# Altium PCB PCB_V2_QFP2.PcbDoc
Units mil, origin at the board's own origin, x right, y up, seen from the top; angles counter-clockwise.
Board outline 5390 x 3140 mil, 2 copper layers (Top Layer, Bottom Layer); 72 components, 66 nets, 285 pads, 52 vias.
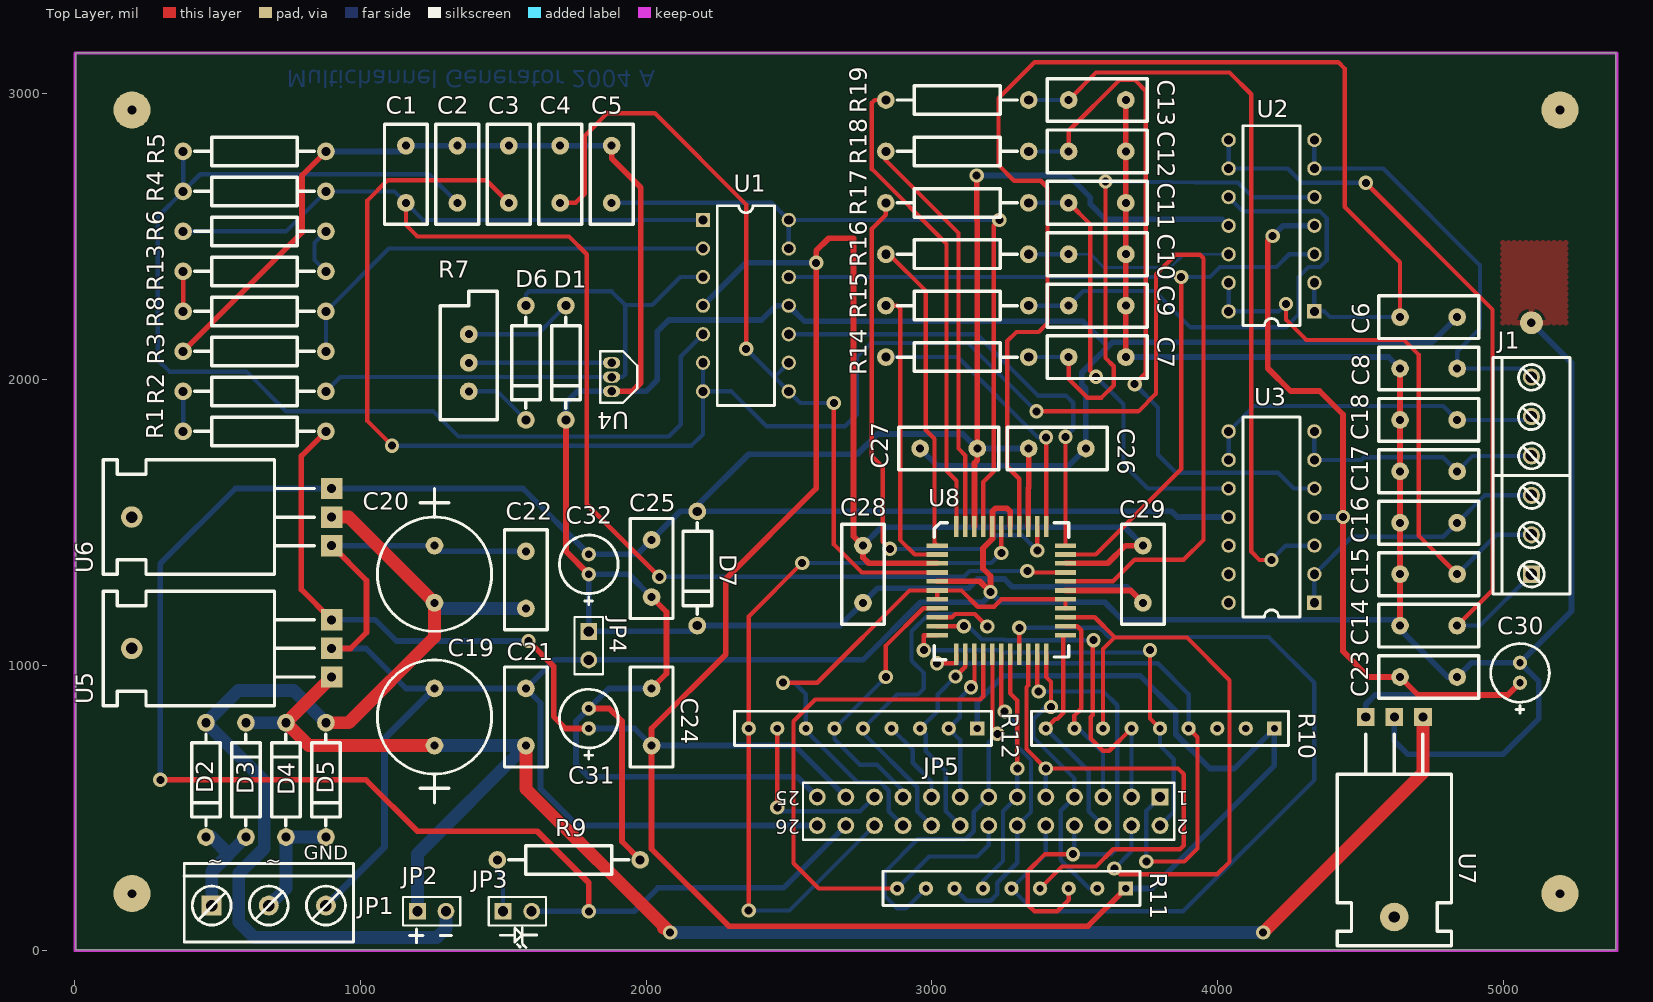
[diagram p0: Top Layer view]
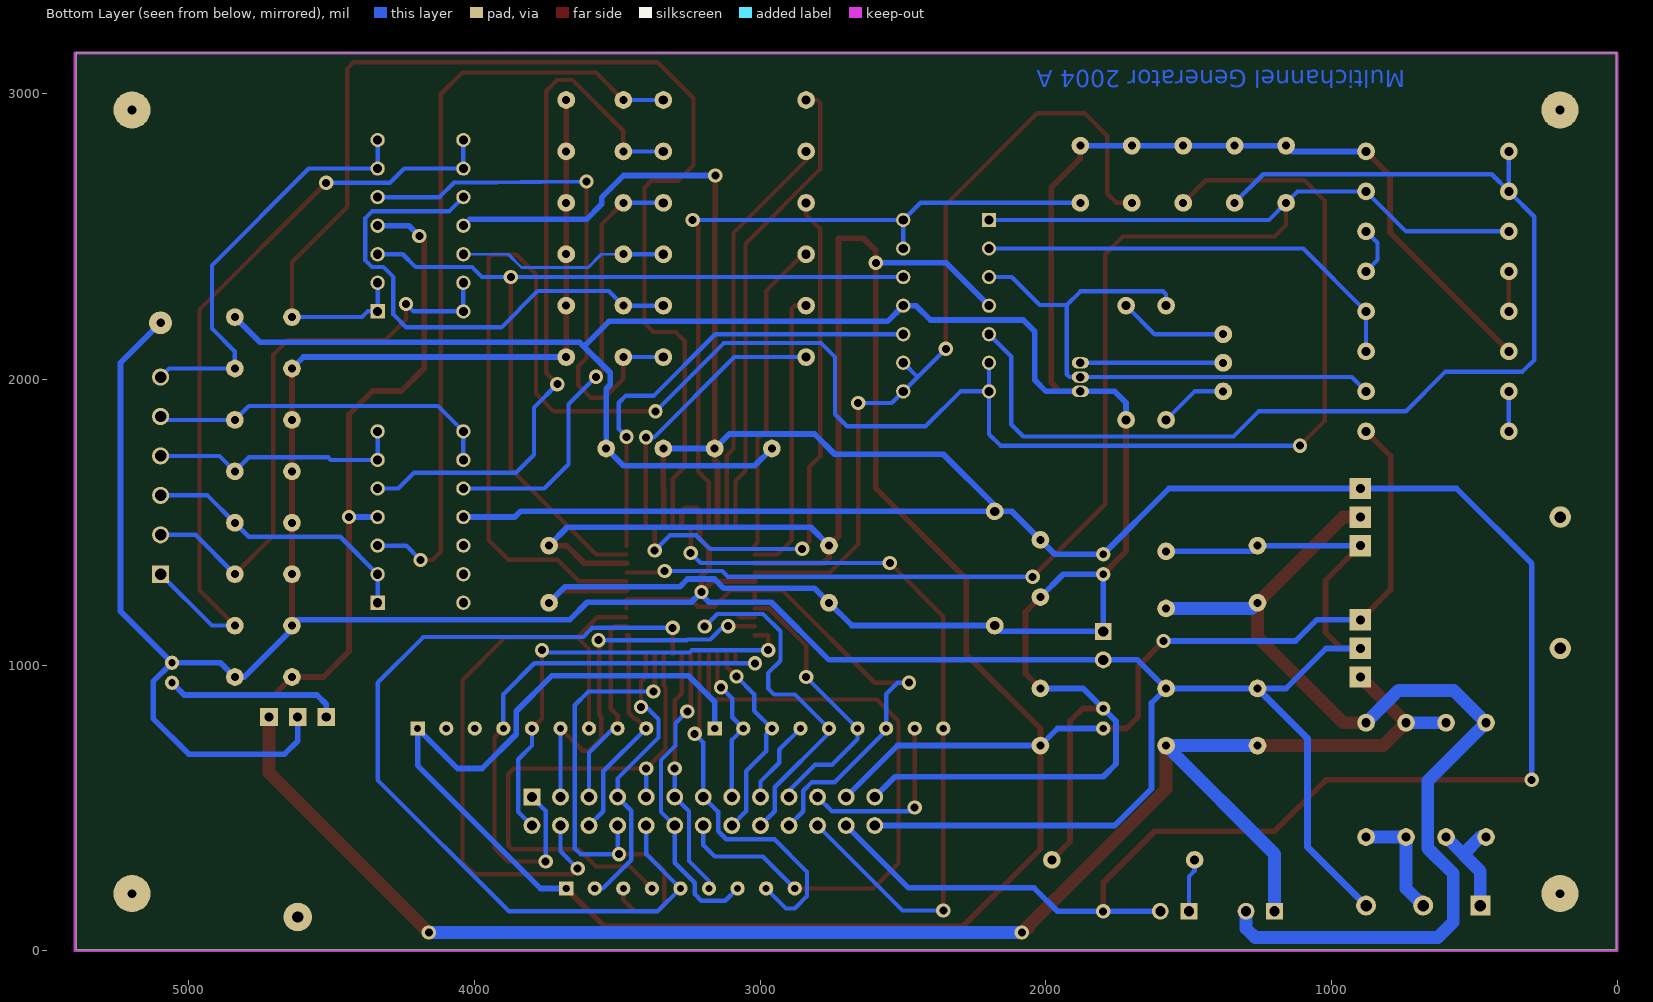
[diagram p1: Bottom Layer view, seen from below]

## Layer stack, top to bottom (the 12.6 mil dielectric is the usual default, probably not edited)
Top Layer: signal copper 1.4
Dielectric: dielectric 12.6, FR-4, Dk 4.8
Bottom Layer: signal copper 1.4

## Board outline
4,3 5394,3 5394,3143 4,3143

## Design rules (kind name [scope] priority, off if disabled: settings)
Clearance [All] p1: gap=10
ComponentClearance [All] p1: gap=10 collisioncheckmode=0
FanoutControl Fanout_SIP [IsSIP] p1: bgadir=In bgaviamode=Closest fanoutstyle=UnderPads fanoutdirection=OutOnly viagrid=1
FanoutControl Fanout_DIP [IsDIP] p2: bgadir=In bgaviamode=Closest fanoutstyle=UnderPads fanoutdirection=OutOnly viagrid=1 // Bez komentarza
FanoutControl Fanout_LCC [IsLCC] p3: bgadir=In bgaviamode=Closest fanoutstyle=Auto fanoutdirection=OutOnly viagrid=1 // Fanout_LCC (Default Rule)
FanoutControl Fanout_BGA [IsBGA] p4: bgadir=Out bgaviamode=Centered fanoutstyle=Auto fanoutdirection=Alternating viagrid=1 // Fanout_BGA (Default Rule)
FanoutControl Fanout_SOIC [IsSOIC] p5: bgadir=Out bgaviamode=Closest fanoutstyle=Auto fanoutdirection=Alternating viagrid=1 // Fanout_SOIC (Default Rule)
FanoutControl Fanout_Default [All] p6: bgadir=Out bgaviamode=Centered fanoutstyle=Auto fanoutdirection=None viagrid=1 // Fanout_Default (Default Rule)
PolygonConnect [All] p1: connectstyle=Relief reliefconductorwidth=10 reliefentries=4 polygonreliefangle="90 Angle"
RoutingLayers [All] p1: top layer=Vertical bottom layer=Horizontal
RoutingVias [All] p1: holewidth=28 width=50 viastyle="Through Hole" minholewidth=28 minwidth=50 maxholewidth=28 maxwidth=50
SolderMaskExpansion [All] p1: expansion=4
TestPointUsage [All] p1: valid=0 allowmultiple=FALSE
Testpoint [All] p1: side=15 testpointundercomponent=TRUE minsize=40 maxsize=100 preferedsize=60 minholesize=0 maxholesize=40 preferedholesize=32 testpointgrid=1 style=1023 order=1234567890
Width 20mil [InNet('VDD') + InNet('VSS') + InNet('AGND') + InNet('GND')+ InNet('+9V')] p1: maxlimit=30 minlimit=10 preferedwidth=10 toplayer_minwidth=15 toplayer_prefwidth=20 bottomlayer_minwidth=15 bottomlayer_prefwidth=20 minimp=50.000000 maximp=50.000000 favimp=50.000000
Width 45mil [InNet('POWER+') + InNet('POWER-') + InNet('POWERA') + InNet('POWERB') + InNet('POWERC') + InNet('POWERD')+ InNet('Net_LM7805')+ InNet('Net_LM7905')] p2: maxlimit=50 minlimit=10 preferedwidth=10 toplayer_minwidth=40 toplayer_prefwidth=45 bottomlayer_minwidth=40 bottomlayer_prefwidth=45 minimp=50.000000 maximp=50.000000 favimp=50.000000
Width 15mil [All] p3: maxlimit=20 minlimit=10 preferedwidth=10 toplayer_prefwidth=15 bottomlayer_prefwidth=15 minimp=50.000000 maximp=50.000000 favimp=50.000000
11 further rules are at their usual default settings.

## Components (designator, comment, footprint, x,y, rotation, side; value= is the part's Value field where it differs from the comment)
C1 "10nF" RAD0.2 1159,2618 r90 top
C2 "10nF" RAD0.2 1339,2618 r90 top
C3 "10nF" RAD0.2 1519,2618 r90 top
C4 "10nF" RAD0.2 1699,2618 r90 top
C5 "10nF" RAD0.2 1879,2618 r90 top
C6 "10nF" RAD0.2 4639,2218 r0 top
C7 "100pF" RAD0.2 3479,2078 r0 top
C8 "100pF" RAD0.2 4839,2038 r180 top
C9 "100pF" RAD0.2 3479,2258 r0 top
C10 "100pF" RAD0.2 3479,2438 r0 top
C11 "100pF" RAD0.2 3479,2618 r0 top
C12 "100pF" RAD0.2 3479,2798 r0 top
C13 "100pF" RAD0.2 3479,2978 r0 top
C14 "100pF" RAD0.2 4839,1138 r180 top
C15 "100pF" RAD0.2 4839,1318 r180 top
C16 "100pF" RAD0.2 4839,1498 r180 top
C17 "100pF" RAD0.2 4839,1678 r180 top
C18 "100pF" RAD0.2 4839,1858 r180 top
C19 "220uF" RB.2/.4 1259,718 r270 top
C20 "220uF" RB.2/.4 1259,1418 r90 top
C21 "100nF" RAD0.2 1579,918 r270 top
C22 "100nF" RAD0.2 1579,1198 r90 top
C23 "100nF" RAD0.2 4839,958 r180 top
C24 "100nF" RAD0.2 2019,918 r270 top (schematic designator C23)
C25 "100nF" RAD0.2 2019,1438 r270 top (schematic designator C24)
C26 "100nF" RAD0.2 3339,1758 r0 top (schematic designator C25)
C27 "100nF" RAD0.2 3159,1758 r180 top (schematic designator C26)
C28 "100nF" RAD0.2 2759,1418 r270 top (schematic designator C27)
C29 "100nF" RAD0.2 3739,1418 r270 top (schematic designator C28)
C30 "10uF" RB.07/.2 5059,938 r90 top
C31 "10uF" RB.07/.2 1799,778 r90 top (schematic designator C29)
C32 "10uF" RB.07/.2 1799,1318 r90 top (schematic designator C30)
D1 "1N4148" DIODE0.4 1719,2258 r270 top
D2 "1N4001" DIODE0.4 459,798 r270 top
D3 "1N4001" DIODE0.4 599,398 r90 top
D4 "1N4001" DIODE0.4 739,398 r90 top
D5 "1N4001" DIODE0.4 879,798 r270 top
D6 "1N4181" DIODE0.4 1579,2258 r270 top
D7 "Schottky" Diode0.4 2179,1538 r270 top
J1 "Term6" TERM6-0.14 5099,1318 r90 top
JP1 "Header 3X1" TERM3-0.2 479,158 r0 top
JP2 "Header 2X1" HDR1X2 1199,138 r0 top
JP3 "Header 2X1" HDR1X2 1499,138 r0 top
JP4 "Header 2X1" HDR1X2 1799,1118 r270 top
JP5 "Header 13X2" HDR2X13 3799,538 r180 top
R1 "100" AXIAL0.5 379,1818 r0 top
R2 "2.4k" AXIAL0.5 879,1958 r180 top
R3 "10k" AXIAL0.5 879,2098 r180 top
R4 "10k" AXIAL0.5 379,2658 r0 top
R5 "10k" AXIAL0.5 879,2798 r180 top
R6 "15k" AXIAL0.5 379,2518 r0 top
R7 "10k" VR5 1379,1958 r90 top
R8 "330" AXIAL0.5 879,2238 r180 top
R9 "330" AXIAL0.5 1979,318 r180 top
R10 "RPACK8" RPACK8 4199,778 r270 top
R11 "RPACK8" RPACK8 3679,218 r270 top
R12 "RPACK8" RPACK8 3159,778 r270 top
R13 "1k2" AXIAL0.5 379,2378 r0 top
R14 "750" AXIAL0.5 2839,2078 r0 top
R15 "750" AXIAL0.5 3339,2258 r180 top
R16 "750" AXIAL0.5 3339,2438 r180 top
R17 "750" AXIAL0.5 3339,2618 r180 top
R18 "750" AXIAL0.5 3339,2798 r180 top
R19 "750" AXIAL0.5 3339,2978 r180 top
U1 "TL084" DIP14 2199,2558 r0 top locked
U2 "LM324" DIP14 4339,2238 r180 top
U3 "LM324" DIP14 4339,1218 r180 top
U4 "LM336Z2.5(3)" TO-92B 1879,1958 r90 top
U5 "LM7805CT" TO-220#1 899,958 r90 top
U6 "LM7905CT" TO-220#1 899,1418 r90 top
U7 "LM7809C" TO-220#2 4719,818 r180 top
U8 "MAX547-QFP44" QFP44-2 3019,1418 r0 top (schematic designator U7)

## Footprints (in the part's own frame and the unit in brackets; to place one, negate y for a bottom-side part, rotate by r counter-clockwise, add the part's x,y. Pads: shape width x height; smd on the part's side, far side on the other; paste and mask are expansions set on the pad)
AXIAL0.5 [mil]
  round 62 hole 32: 1(0,0) 2(500,0)
  silkscreen extent 40,-50 460,50
DIODE0.4 [mil]
  round 62 hole 32: 1(0,0) 2(400,0)
  silkscreen extent 40,-50 360,50
Diode0.4 [mil]
  round 62 hole 32: 1(0,0) 2(400,0)
  silkscreen extent 40,-50 360,50
DIP14 [mil]
  rect 50x50 hole 32: 1(0,0)
  round 50 hole 32: 2(0,-100) 3(0,-200) 4(0,-300) 5(0,-400) 6(0,-500) 7(0,-600) 8(300,-600) 9(300,-500) 10(300,-400) 11(300,-300) 12(300,-200) 13(300,-100) 14(300,0)
  silkscreen extent 50,-650 250,50
HDR1X2 [mm]
  rect 1.5x1.5 hole 0.9: 1(0,0)
  round 1.5 hole 0.9: 2(2.54,0)
  silkscreen extent -1.27,-1.27 3.81,1.27
HDR2X13 [mm]
  rect 1.5x1.5 hole 0.9: 1(0,0)
  round 1.5 hole 0.9: 2(0,2.54) 3(2.54,0) 4(2.54,2.54) 5(5.08,0) 6(5.08,2.54) 7(7.62,0) 8(7.62,2.54) 9(10.16,0) 10(10.16,2.54) 11(12.7,0) 12(12.7,2.54) 13(15.24,0) 14(15.24,2.54) 15(17.78,0) 16(17.78,2.54) 17(20.32,0) 18(20.32,2.54) 19(22.86,0) 20(22.86,2.54) 21(25.4,0) 22(25.4,2.54) 23(27.94,0) 24(27.94,2.54) 25(30.48,0) 26(30.48,2.54)
  silkscreen extent -1.27,-1.27 31.75,3.81
QFP44-2 [mil]
  rect 75x16 smd: 1(0,0) 2(0,-31) 3(0,-62) 4(0,-94) 5(0,-125) 6(0,-157) 7(0,-188) 8(0,-219) 9(0,-251) 10(0,-282) 11(0,-314) 23(449,-314) 24(449,-282) 25(449,-251) 26(449,-219) 27(449,-188) 28(449,-157) 29(449,-125) 30(449,-94) 31(449,-62) 32(449,-31) 33(449,0)
  rect 16x75 smd: 12(67,-381) 13(98,-381) 14(130,-381) 15(161,-381) 16(193,-381) 17(224,-381) 18(255,-381) 19(287,-381) 20(318,-381) 21(350,-381) 22(381,-381) 34(381,67) 35(350,67) 36(318,67) 37(287,67) 38(255,67) 39(224,67) 40(193,67) 41(161,67) 42(130,67) 43(98,67) 44(67,67)
  silkscreen extent -10,-400 460,80
RAD0.2 [mil]
  round 62 hole 28: 1(0,0) 2(200,0)
  silkscreen extent -75,-75 275,75
RB.2/.4 [mil]
  round 62 hole 28: 1(0,0) 2(-200,0)
  silkscreen extent -300,-200 200,200
RB.07/.2 [mil]
  round 50 hole 25: 1(0,0) 2(70,0)
  silkscreen extent -107,-103 137,102
RPACK8 [mil]
  rect 50x50 hole 25: 1(0,0)
  round 50 hole 25: 2(0,-100) 3(0,-200) 4(0,-300) 5(0,-400) 6(0,-500) 7(0,-600) 8(0,-700) 9(0,-800)
  silkscreen extent -60,-850 60,50
TERM3-0.2 [mil]
  rect 70x70 hole 40: 1(0,0)
  round 70 hole 40: 2(200,0) 3(400,0)
  silkscreen extent -97,-128 496,147
TERM6-0.14 [mil]
  rect 60x60 hole 40: 1(0,0)
  round 60 hole 40: 2(138,0) 3(276,0) 4(414,0) 5(552,0) 6(690,0)
  silkscreen extent -69,-135 759,135
TO-92B [mil]
  oval 40x60 hole 30: 1(0,0) 2(50,0) 3(100,0)
  silkscreen extent -40,-90 140,40
TO-220#1 [mil]
  round 75 hole 40: 0(100,700)
  rect 75x75 hole 32: 1(0,0) 2(100,0) 3(200,0)
  silkscreen extent -100,60 300,800
TO-220#2 [mil]
  round 100 hole 40: 0(100,700)
  rect 62x62 hole 32: 1(0,0) 2(100,0) 3(200,0)
  silkscreen extent -100,60 300,800
VR5 [mil]
  round 62 hole 28: 1(0,0) 2(100,0) 3(200,0)
  silkscreen extent -100,-100 350,100

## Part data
C1 C2 C3 C4 C5 C6 C7 C8 C9 C10 C11 C12 C13 C14 C15 C16 C17 C18 C21 C22 C23 C24 C25 C26 C27 C28 C29: library part CAP, "Capacitor"
C19 C20 C30 C31 C32: library part ELECTRO1, "Electrolytic Capacitor"
D1 D6: library part DIODE, "Diode"
D2 D3 D4 D5 D7: library part Diode, "Default Diode"
JP1: library part "Header 3", "Header, 3-Pin"
JP2 JP3 JP4: library part "Header 2", "Header, 2-Pin"
JP5: "Header, 13-Pin, Dual row"
R1 R2 R3 R4 R5 R6 R8 R9 R13 R14 R15 R16 R17 R18 R19: library part RES2
R7: library part RPot2, "Potentiometer"
U1: "JFET-Input Operational Amplifiers"
U2 U3: library part TL084, "JFET-Input Operational Amplifiers"
U4: "ADJUSTABLE MICROPOWER VOLTAGE REFERENCES"
U5: library part MC7805T
U6: library part MC7905T

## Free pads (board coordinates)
  round 130 hole 30: 0(200,200) 0(200,2943) 0(5199,200) 0(5199,2943)
  round 80 hole 30: 1(5099,2198)

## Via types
v1: diameter 50, hole 28, Top Layer to Bottom Layer, 52 vias

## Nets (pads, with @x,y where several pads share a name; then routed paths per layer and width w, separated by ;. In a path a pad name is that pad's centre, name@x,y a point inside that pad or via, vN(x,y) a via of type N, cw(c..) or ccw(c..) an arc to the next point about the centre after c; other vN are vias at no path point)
+9V: C23.2 C30.1 U2.4 U3.4 U7.3 | length 3207.3
  Top Layer w20: v1(4193,2502) 4176,2485 4176,2039 4256,1959 4357,1959 4439,1877 4439,1048 4529,958 C23.2 4702,895 5016,895 C30.1
  Bottom Layer w20: v1(4193,2502) 4229,2538 U2.4 ; U3.4 v1(4439,1518) ; U7.3 4519,863 4551,895 5016,895 C30.1
/IOS: JP5.19 R12.6 U8.8 | length 973.4
  Top Layer w15: v1(2839,958) 2839,1068 2970,1199 U8.8
  Bottom Layer w15: v1(2839,958) R12.6 2659,740 2748,651 2808,651 2899,560 JP5.19
/WR: JP5.18 R12.5 U8.9 | length 1434.9
  Top Layer w15: U8.9 3070,1167 3082,1179 3150,1179 v1(3194,1135)
  Bottom Layer w15: JP5.18 2949,488 2949,572 2759,762 R12.5 2878,897 2951,897 2972,918 2972,972 2929,1015 2929,1118 2990,1179 3150,1179 v1(3194,1135)
A0: JP5.1 R10.4 U8.12 | length 2021.5
  Top Layer w15: v1(3018,1006) 3086,1006 U8.12 ; v1(3751,312) 3884,312 3930,358 3930,747 R10.4
  Bottom Layer w15: v1(3018,1006) 3791,1006 3899,898 R10.4 ; v1(3751,312) 3751,490 JP5.1
A1: JP5.2 R10.5 U8.11 | length 1565.9
  Top Layer w15: v1(2972,1052) 2972,1104 U8.11 ; v1(3764,1052) 3764,813 R10.5
  Bottom Layer w15: v1(2972,1052) 3239,1052 3247,1044 3756,1044 v1(3764,1052) ; JP5.2 3847,486 3847,670 3799,718 R10.5
A2: JP5.3 R10.6 U8.10 | length 1350.3
  Top Layer w15: U8.10 v1(3112,1136) ; v1(3566,1087) 3563,1087 3563,825 3556,818 3556,743 3599,700 3621,700 R10.6
  Bottom Layer w15: v1(3112,1136) 3128,1136 3175,1089 3254.68,1089 3256.68,1087 v1(3566,1087) ; JP5.3 R10.6
AGND: C7.2 C8.2 C9.2 C10.2 C11.2 C12.2 C13.2 C14.2 C15.2 C16.2 C17.2 C18.2 C19.2 C20.1 C21.1 C22.2 C23.1 C30.2 JP1.3 JP4.2 JP5.26 pad.1 U5.2 U6.1 U7.2 U8.5 U8.38 U8.40 | length 13639.8
  Top Layer w20: U5.2 965,1058 1021,1114 1021,1296 U6.1 ; U8.5 3168,1293 v1(3205,1256) 3205,1312 3179,1338 3179,1409 3212,1442 U8.40 3212,1538 3223,1549 3263,1549 3274,1538 U8.38 ; C7.2 C9.2 C10.2 C11.2 C12.2 C13.2 ; C14.2 C15.2 C16.2 C17.2 C18.2 C8.2
  Bottom Layer w20: U5.2 1019,1058 1159,918 C21.1 ; U6.1 C20.1 1279,1398 C22.2 ; JP5.26 1759,438 1630,567 1630,867 C21.1 ; C7.2 4599,2078 C8.2 ; U7.2 4619,734 4665,688 5000,688 5125,813 5125,942 C30.2 ; C14.2@4619,1158 C14.2 C14.2@4639,1118 ; C14.2@4622,1158 3667,1158 3605,1220 3241,1220 v1(3205,1256) 3205,1246 3179,1220 2961,1220 2759,1018 JP4.2 1679,1018 C21.1 ; C14.2@4639,1125 4806,958 C23.1 4889,1008 C30.2 ; pad.1 5239,2058 5239,1188 C30.2
  Bottom Layer w25: JP1.3 1084,363 1084,743 C19.2
D8: JP5.4 R10.7 U8.25 | length 2240.8
  Top Layer w15: U8.25 3570,1167 3639,1098 3639,1096 ; R10.7 3599,1056 3639,1096 ; v1(3639,288) 3659,268 3999,268 4042,311 4042,947 3893,1096 3639,1096
  Bottom Layer w15: v1(3639,288) 3699,348 JP5.4
D9: JP5.5 R10.8 U8.24 | length 704.9
  Top Layer w15: U8.24 3509,1136 3523,1122 3523,847 3499,823 R10.8
  Bottom Layer w15: R10.8 3514,778 3599,693 JP5.5
D10: JP5.6 R10.9 U8.23 | length 786.2
  Top Layer w15: R10.9 3432,811 3439,811 3460,832 3460,1104 U8.23
  Bottom Layer w15: R10.9 3549,628 3549,488 JP5.6
D11: JP5.7 R11.2 U8.22 | length 1010.4
  Top Layer w15: U8.22 3400,958 3417,941 v1(3417,853)
  Bottom Layer w15: v1(3417,853) 3399,853 3356,810 3356,746 3499,603 JP5.7 3451,490 3451,318 3551,218 R11.2
D12: JP5.8 R11.3 U8.21 | length 1702.3
  Top Layer w15: U8.21 3369,912 v1(3374,907) ; R11.3 3479,178 3439,138 3359,138 3336,161 3336,278 3396,338 v1(3494,338)
  Bottom Layer w15: v1(3374,907) 3601,907 3649,859 3649,358 3629,338 v1(3494,338) 3499,343 JP5.8
D13: JP5.9 R11.4 U8.20 | length 1836.1
  Top Layer w15: U8.20 3337,928 3331,922 3331,706 v1(3399,638) 3862,638 3882,618 3882,368 3869,355 3635,355 3575,295 3456,295 R11.4
  Bottom Layer w15: JP5.9 v1(3399,638)
D14: JP5.10 R11.5 U8.19 | length 3099.5
  Top Layer w15: U8.19 v1(3306,1130)
  Bottom Layer w15: v1(3306,1130) 3588,1130 3608,1110 3608,1109 3619,1098 4179,1098 4339,938 4339,598 3879,138 3359,138 R11.5 3399,338 JP5.10
D15: JP5.11 R11.6 U8.18 | length 879.1
  Top Layer w15: U8.18 3274,901 3299,876 v1(3299,638)
  Bottom Layer w15: R11.6 3179,244 3249,314 3249,488 JP5.11 v1(3299,638)
D16: JP5.12 R11.7 U8.17 | length 1108.3
  Top Layer w15: U8.17 3243,849 v1(3255,837)
  Bottom Layer w15: R11.7 3122,175 3206,175 3229,198 3229,238 3299,308 JP5.12 3347,486 3347,667 3296,718 3296,796 v1(3255,837)
D17: JP5.13 R11.8 U8.16 | length 1304.6
  Top Layer w15: U8.16 3212,776 v1(3229,759)
  Bottom Layer w15: R11.8 2909,148 2879,148 2836,191 2836,276 2950,390 3119,390 3147,418 3147,486 JP5.13 3199,729 v1(3229,759)
D18: JP5.14 R11.9 U8.15 | length 2194.4
  Top Layer w15: R11.9 2604,218 2516,306 2516,803 2592,879 3169,879 3180,890 U8.15
  Bottom Layer w15: R11.9 2991,330 3159,330 3199,370 JP5.14
D19: JP5.15 R12.2 U8.14 | length 552.8
  Top Layer w15: v1(3137,922) 3149,934 U8.14
  Bottom Layer w15: JP5.15 3099,738 R12.2 3098,817 3098,883 v1(3137,922)
D20: JP5.16 R12.3 U8.13 | length 722.4
  Top Layer w15: v1(3083,960) 3117,994 U8.13
  Bottom Layer w15: v1(3083,960) 3021,898 3021,840 R12.3 2979,758 2979,698 3049,628 3049,488 JP5.16
D21: JP5.17 R12.4 | length 298
  Bottom Layer w15: R12.4 2933,704 2933,658 2999,592 JP5.17
FL0: JP5.20 R12.7 U8.6 U8.7 U8.26 U8.27 | length 1963.4
  Top Layer w15: v1(2479,938) 2599,938 2922,1261 U8.6 ; U8.7 U8.6 ; U8.26 U8.27 3244,1230 3218,1204 3161,1204 3104,1261 U8.6
  Bottom Layer w15: v1(2479,938) 2519,938 2559,898 2559,770 2739,590 2819,590 2849,560 2849,488 JP5.20
FL1: JP5.21 R12.8 | length 643.1
  Top Layer w15: v1(2459,501) R12.8
  Bottom Layer w15: v1(2459,501) 2472,488 2749,488 JP5.21
FL2: JP5.22 R12.9 U8.39 | length 2661
  Top Layer w15: v1(2359,141) 2359,728 2359,753 R12.9 2359,1170 v1(2546,1357) ; v1(3243,1392) U8.39
  Bottom Layer w15: v1(2359,141) 2502,141 JP5.22 ; v1(2546,1357) 3208,1357 v1(3243,1392)
GND: C1.2 C2.2 C3.2 C4.2 C5.2 C6.2 C24.1 C25.2 C26.2 C27.2 C28.2 C29.2 C31.2 C32.1 D1.2 D7.2 JP4.1 JP5.25 R3.2 R5.1 R9.1 U1.11 U4.1 U8.28 | length 13184.8
  Top Layer w20: R3.2 795,2514 795,2714 R5.1 ; D1.2 1719,1398 C32.1 ; C31.2 1871,848 1915,804 1915,382 R9.1 ; U4.1 1951,1958 1981,1988 1981,2672 1879,2774 C5.2 ; C24.1 2071,970 2071,1186 C25.2 ; U8.28 3696,1261 C29.2
  Bottom Layer w20: R5.1 1139,2798 C1.2 C2.2 C3.2 C4.2 C5.2 ; D1.2 1719,1918 1759,1958 U4.1 1999,1958 2039,1998 2039,2168 2079,2208 2404,2208 2454,2258 U1.11 2554,2203 3529,2203 3617,2115 ; C24.1 1869,918 C31.2 1754,803 1754,654 1799,609 2528,609 JP5.25 ; C25.2 1939,1318 C32.1 JP4.1 2159,1118 D7.2 2679,1138 C28.2 2810,1269 3128,1269 3160,1301 3254,1301 3281,1274 3683,1274 C29.2 ; C27.2 3019,1698 3479,1698 C26.2 3539,1967 3525,1981 3525,2023 3632,2130 4751,2130 C6.2
NET_LM7805: C19.1 C21.2 D3.2 D4.2 JP2.1 U5.1 U7.1 | length 5930.4
  Top Layer w45: U5.1 D4.2 819,718 C19.1 ; C21.2 1579,566 v1(2084,64) 2061,80 ; v1(4160,64) 4719,623 U7.1
  Bottom Layer w45: D3.2 D4.2 ; JP2.1 1199,338 C21.2 C19.1 ; v1(2084,64) v1(4160,64)
NET_LM7905: C20.2 C22.1 D2.1 D5.1 JP2.2 U6.2 | length 3590.4
  Top Layer w45: D5.1 959,798 1259,1098 C20.2 959,1518 U6.2
  Bottom Layer w45: D5.1 766,911 572,911 D2.1 663,594 663,359 574,270 574,100 628,46 1267,46 1299,78 JP2.2 ; C20.2 1279,1198 C22.1
NetC1_1: C1.1 R4.2 R6.1 U1.1 U8.30 | length 5339.2
  Top Layer w15: C1.1 1159,2540 1199,2500 1730,2500 1792,2438 1792,1563 v1(2046,1309) ; v1(3334,1329) 3339,1324 U8.30
  Bottom Layer w15: R6.1 739,2518 R4.2 1119,2658 C1.1 1219,2558 U1.1 ; v1(2046,1309) 3113,1309 3133,1329 v1(3334,1329)
NetC2_1: C2.1 R4.1 R5.2 U1.5 | length 4100.9
  Bottom Layer w15: R5.2 R4.1 ; C2.1 1239,2718 439,2718 R4.1 ; U1.5 2121,2080 2121,1842 2079,1800 1343,1800 1255,1888 740,1888 601,2027 331,2027 290,2068 290,2569 R4.1
NetC3_1: C3.1 U1.6 U1.7 U8.29 | length 6951.4
  Top Layer w15: v1(1110,1768) 1024,1854 1024,2626 1095,2697 1440,2697 C3.1 ; v1(3366,1888) 3723,1888 3785,1950 3785,2368 3853,2436 3939,2436 3951,2424 3951,1438 3882,1369 3710,1369 3634,1293 U8.29
  Bottom Layer w15: v1(1110,1768) 2159,1768 2199,1808 U1.7 ; U1.6 U1.7 ; v1(3366,1888) 3127,2127 2787,2127 2738,2078 2738,1878 2696,1836 2421,1836 2299,1958 U1.7
NetC7_1: C7.1 R14.2 U2.5 | length 1897.5
  Top Layer w15: C7.1 3479,2001 3544,1936 3594,1936 3637,1979 3637,2046 3608,2075 v1(3608,2693)
  Bottom Layer w15: R14.2 C7.1 ; v1(3608,2693) 4072,2688 4122,2638 U2.5
NetC8_1: C8.1 J1.6 U2.6 U2.7 | length 1487
  Bottom Layer w15: U2.7 U2.6 4580,2738 4919,2399 4919,2178 4839,2098 C8.1 5069,2038 J1.6
NetC9_1: C9.1 R15.1 U2.10 | length 1812.6
  Bottom Layer w15: R15.1 C9.1 3530,2309 3779,2309 3906,2182 4239,2182 4284,2227 4284,2358 4319,2393 4359,2393 4382,2416 4382,2565 4359,2588 4089,2588 U2.10
NetC10_1: C10.1 R16.1 U2.12 | length 738.1
  Bottom Layer w10: C10.1 3556,2438 3602,2392 3836,2392 3882,2438 U2.12
  Bottom Layer w15: R16.1 C10.1
NetC11_1: C11.1 R17.1 U3.10 | length 1537.7
  Top Layer w15: C11.1 3555,2542 3555,2029 v1(3575,2009)
  Bottom Layer w15: R17.1 C11.1 ; v1(3575,2009) 3671,1913 3671,1703 3756,1618 U3.10
NetC12_1: C12.1 R18.1 U3.5 | length 2491.5
  Top Layer w15: C12.1 3479,2870 3657,3048 3711,3048 3749,3010 3749,2022 v1(3710,1983)
  Bottom Layer w15: R18.1 C12.1 ; v1(3710,1983) 3792,1901 3792,1736 3855,1673 4212,1673 4267,1618 U3.5
NetC13_1: C13.1 R19.1 U3.3 | length 2705
  Top Layer w15: C13.1 3575,3074 4042,3074 4118,2998 4118,1397 4147,1368 v1(4189,1368)
  Bottom Layer w15: R19.1 C13.1 ; v1(4189,1368) 4239,1418 U3.3
NetC14_1: C14.1 J1.1 U2.8 U2.9 | length 2720.5
  Top Layer w15: v1(4519,2688) 4963,2244 4963,1262 C14.1
  Bottom Layer w15: U2.8 U2.9 4246,2738 4296,2688 v1(4519,2688) ; C14.1 4919,1138 J1.1
NetC15_1: C15.1 J1.2 U2.13 U2.14 | length 2023.4
  Top Layer w15: v1(4240,2264) 4240,2209 4311,2138 4653,2138 4704,2087 4704,1453 C15.1
  Bottom Layer w15: U2.13 U2.14 4214,2238 v1(4240,2264) ; C15.1 4977,1456 J1.2
NetC16_1: C16.1 J1.3 U3.1 U3.2 | length 974.3
  Bottom Layer w15: U3.1 U3.2 4470,1449 4790,1449 C16.1 4935,1594 J1.3
NetC17_1: C17.1 J1.4 U3.6 U3.7 | length 906.4
  Bottom Layer w15: U3.7 U3.6 4503,1718 4512,1727 4790,1727 C17.1 4893,1732 J1.4
NetC18_1: C18.1 J1.5 U3.8 U3.9 | length 1222.1
  Bottom Layer w15: U3.9 U3.8 4128,1907 4790,1907 C18.1 5087,1858 J1.5
NetD1_1: D1.1 R7.3 | length 381.4
  Bottom Layer w15: R7.3 1619,2158 D1.1
NetD6_1: D6.1 R2.1 U1.3 U4.2 | length 2039.5
  Bottom Layer w15: R2.1 929,2008 U4.2 1917,2008 1927,2018 1927,2260 ; D6.1 1579,2298 1589,2308 1879,2308 1927,2260 ; U1.3 2119,2358 2021,2260 1927,2260
NetD6_2: D6.2 R7.1 | length 241.4
  Bottom Layer w15: R7.1 1479,1958 D6.2
NetJP3_1: JP3.1 R9.2 | length 188.3
  Bottom Layer w15: R9.2 1479,280 1499,260 JP3.1
NetR1_1: R1.1 R2.2 | length 140
  Bottom Layer w15: R1.1 R2.2
NetR3_1: R3.1 R8.1 U1.2 | length 1551.1
  Bottom Layer w15: R3.1 R8.1 1099,2458 U1.2
NetR6_2: R6.2 R13.2 | length 173.1
  Bottom Layer w15: R13.2 839,2418 839,2478 R6.2
NetR7_2: R7.2 U4.3 | length 500
  Bottom Layer w15: R7.2 U4.3
NetR8_2: R8.2 R13.1 | length 140
  Top Layer w15: R8.2 R13.1
NetR14_1: R14.1 U8.34 | length 989.4
  Top Layer w15: U8.34 v1(3400,1797)
  Bottom Layer w15: R14.1 3091,2078 3372,1797 v1(3400,1797)
NetR15_2: R15.2 U8.2 | length 1015.3
  Top Layer w15: R15.2 2879,2258 2889,2248 2889,1438 2940,1387 U8.2
NetR16_2: R16.2 U8.1 | length 1101
  Top Layer w15: R16.2 2850,2438 2979,2309 2979,1822 3009,1792 3009,1428 U8.1
NetR17_2: R17.2 U8.35 | length 1898.9
  Top Layer w15: R17.2 2839,2576 2790,2527 2790,1731 2828,1693 2828,1432 v1(2853,1407) ; v1(3369,1401) U8.35
  Bottom Layer w15: v1(2853,1407) 3175,1406 3224,1454 3316,1454 v1(3369,1401)
NetR18_2: R18.2 U8.43 | length 1428.2
  Top Layer w15: R18.2 2839,2766 3093,2512 3093,1757.75 3117,1733.75 U8.43
NetR19_2: R19.2 U8.44 | length 1658.7
  Top Layer w15: R19.2 2800,2978 2790,2968 2790,2736 3051,2475 3051,1680 3086,1645 U8.44
NetU1_10: U1.10 U8.33 | length 1606.6
  Top Layer w15: U8.33 v1(3468,1799)
  Bottom Layer w15: U1.10 3157,2158 3372,1943 3470,1943 3495,1918 3495,1826 v1(3468,1799)
NetU1_12: U1.12 U2.3 U8.32 | length 3074
  Top Layer w15: U8.32 3574,1387 3873,1686 v1(3873,2358)
  Bottom Layer w15: U1.12 v1(3873,2358) 3974,2358 4009,2393 4206,2393 4251,2438 U2.3
POWERC: D2.2 D3.1 JP1.1 | length 394.6
  Bottom Layer w45: D2.2 479,398 539,338 ; JP1.1 479,278 D3.1
POWERD: D4.1 D5.2 JP1.2 | length 404.9
  Bottom Layer w45: JP1.2 739,218 D4.1 D5.2
REFAB: C4.1 U1.8 U1.9 U8.4 | length 2890.5
  Top Layer w15: C4.1 1753,2618 1785,2650 1785,2852 1865,2932 2030,2932 2350,2612 v1(2350,2107) ; v1(2657,1917) 2657,1422 2755,1324 U8.4
  Bottom Layer w15: v1(2350,2107) U1.8 2539,1918 v1(2657,1917) ; 2449,2008 U1.9
REFCD: C5.1 U1.13 U1.14 U8.41 | length 2578
  Top Layer w15: U8.41 3180,1641 3217,1678 3217,2539 v1(3236,2558)
  Bottom Layer w15: C5.1 2439,2618 U1.14 ; U1.13 U1.14 ; v1(3236,2558) U1.14
REFEF: C6.1 U2.1 U2.2 U8.37 | length 4378.2
  Top Layer w15: U8.37 3306,1652 3264,1694 3264,2134 3296,2166 3374,2166 3405,2197 3405,2671 3381,2695 3288,2695 3233,2750 3233,2984 3359,3110 4423,3110 4445,3088 4445,2604 4639,2410 C6.1
  Bottom Layer w15: U2.2 U2.1 4374,2238 4394,2218 C6.1
VDD: C24.2 C28.1 C29.1 C31.1 JP5.23 R1.2 R10.1 R11.1 R12.1 U1.4 U5.3 U8.3 U8.31 | length 12633.4
  Top Layer w20: R1.2 793,1732 793,1264 U5.3 ; v1(1588,1084) 1676,996 1676,820 1718,778 C31.1 ; U8.3 2779,1356 2759,1376 C28.1 2726,1451 2726,2494 2639,2494 2595,2450 2595,1618 2279,1302 2279,1038 2019,778 2019,356 2289,86 3547,86 R11.1 ; U8.31 3616,1356 3678,1418 C29.1
  Bottom Layer w20: U5.3 1052,1158 1126,1084 v1(1588,1084) ; C31.1 1959,778 C24.2 2519,718 JP5.23 ; U1.4 2349,2408 v1(2595,2408) ; C28.1 2823,1482 3675,1482 C29.1 ; R12.1 3159,871 3250,962 3730,962 3854,838 3854,758 3974,638 4059,638 R10.1 4199,648 3769,218 R11.1
VSS: C25.1 C26.1 C27.1 C32.2 D7.1 JP3.2 JP5.24 U2.11 U3.11 U6.3 U8.36 U8.42 | length 11524
  Top Layer w20: v1(299,598) 1019,598 1199,418 1619,418 1799,238 v1(1799,138) ; U8.42 3149,1707 3159,1717 C27.1 3159,2556 ; 3157,2558 v1(3157,2714) ; U8.36 3337,1619 3339,1621 C26.1
  Bottom Layer w20: v1(299,598) 299,1355 562,1618 1569,1618 C32.2 1969,1388 2119,1538 3839,1538 3859,1518 U3.11 ; JP3.2 1959,138 2041,220 2481,220 JP5.24 ; D7.1 2179,1558 2359,1738 2739,1738 2810,1809 3108,1809 C27.1 C26.1 ; v1(3157,2714) 3478,2714 3555,2637 3555,2613 3608,2560 4017,2560 U2.11
pads on no net: R10.2 R10.3 U3.12 U3.13 U3.14 U5.0 U6.0 U7.0

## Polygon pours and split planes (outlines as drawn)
AGND on Top Layer (hatched 45Degree grid 0 track 20): 5099,2198 5219,2198 5219,2478 4999,2478 4999,2198

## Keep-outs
Keep-Out Layer:
  lines w10: 0,0 0,3143 5399,3143 5399,0 0,0

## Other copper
Bottom Layer:
  text "Multichannel Generator 2004 A" at 742,3082 h60 r180

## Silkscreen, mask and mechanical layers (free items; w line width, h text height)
Top Overlay:
  lines w10: 1172,53 1219,53 ; 1196,28 1196,76 ; 1279,53 1319,53 ; 1489,54 1540,54 ; 1549,22 1559,12 ; 1566,29 1566,79 ; 1569,21 1579,11 ; 1617,55 1565,55 ; 1565,55 1541,79 1540,78 1540,30 1565,55
  text "GND" at 801,318 h50
  text "~" at 464,292 h50
  text "~" at 667,292 h50

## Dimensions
0,0 to 5399,0 on Mechanical 1
5399,3143 to 5399,0 on Mechanical 1
200,2943 to 0,3143 on Mechanical 1
0,3143 to 200,2943 on Mechanical 1
200,134 to 200,266 on Mechanical 1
